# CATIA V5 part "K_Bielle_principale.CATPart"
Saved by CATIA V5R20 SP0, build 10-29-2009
Part number: Bielle_principale
Bounding box of the stored display mesh (mm): x -665 to -75.005, y -279.606 to -5, z 35.005 to 253.803
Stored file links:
  G:\Khaled_CFAO_2011\ST2M\ST2M_GR2\jcoetard\Khaled\CAD_CATIA\K_Bielle_principale.CATPart
  J:\Thinkmotion\Thinkmotion_COETARD\Maquette_catia\Maquette_catia_R20_Licence_education\jcharlescoetard.CATPRODUCT\Assemblage_Pince_Prehension_Mors_Paralleles.CATProduct
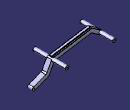
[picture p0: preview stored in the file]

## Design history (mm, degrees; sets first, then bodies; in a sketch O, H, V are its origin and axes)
Set1
  Plane1 "Plan_bielle_principale": linked copy from another document
  Point1 to Point3: linked copy from another document
Body1 (main body)
  Sketch1 on Plane1, origin (0, -122.303, 0), H (-1, 0, 0), V (0, 0, 1)
    construction line L1 (90, 50) -> (204.738, 94.0206)
    point P2 (204.738, 94.0206)
    line L2 (84.627, 64.0047) -> (187.0671, 103.307)
    line L3 (210.111, 80.0159) -> (95.373, 35.9953)
    arc A1 centre (90, 50) radius 15 from (95.373, 35.9953) to (84.627, 64.0047) cw
    construction line L4 (204.738, 94.0206) -> (250, 180)
    point P6 (204.738, 94.0206)
    line L5 (197.6006, 112.6634) -> (236.7268, 186.9874)
    line L6 (255.0898, 157.4677) -> (218.0112, 87.0332)
    arc A2 centre (250, 180) radius 15 from (236.7268, 186.9874) to (247.6716, 194.8182) cw
    arc A3 centre (204.738, 94.0206) radius 15 from (218.0112, 87.0332) to (210.111, 80.0159) cw
    construction line L7 (250, 180) -> (576, 231.225)
    point P11 (576, 231.225)
    line L8 (247.6716, 194.8182) -> (573.6716, 246.0432)
    line L9 (564.4914, 214.2326) -> (269.6828, 167.9088)
    arc A4 centre (576, 231.225) radius 15 from (573.6716, 246.0432) to (584.5375, 243.5583) cw
    construction line L10 (576, 231.225) -> (650, 180)
    point P14 (576, 231.225)
    line L11 (584.5375, 243.5583) -> (658.5375, 192.3333)
    line L12 (641.4625, 167.6667) -> (578.9792, 210.9194)
    arc A5 centre (650, 180) radius 15 from (658.5375, 192.3333) to (641.4625, 167.6667) cw
    arc A6 centre (179.9031, 121.9799) radius 20 from (187.0671, 103.307) to (197.6006, 112.6634) ccw
    point P21 (179.9031, 121.9799)
    arc A7 centre (272.7874, 148.1512) radius 20 from (255.0898, 157.4677) to (269.6828, 167.9088) cw
    point P24 (272.7874, 148.1512)
    arc A8 centre (567.5959, 194.475) radius 20 from (564.4914, 214.2326) to (578.9792, 210.9194) cw
    point P27 (567.5959, 194.475)
    reference projected point E1 (250, 180) from Point1
    reference projected point E2 (90, 50) from Point2
    reference projected point E3 (250, 180) from Point1
    reference projected point E4 (650, 180) from Point3
    distance L2 L3 = 30
    distance L5 L6 = 30
    distance L8 L9 = 30
    distance L11 L12 = 30
    radius A6 = 20
    radius A7 = 20
    radius A8 = 20
    distance P6 P21 = 37.3965
    distance P24 E1 = 39.1614
    distance P27 L10 = 35
    tangency: A1 L2, A1 L3, A2 L5, A3 L5, A2 L6, A3 L6, A4 L8, A4 L9, A5 L11, A5 L12, A6 L2, A6 L5, A7 L6, A7 L9, A8 L9, A8 L12, A2 L8, L3 A3, L11 A4
    coincidence: P6 P2, P14 P11
    concentricity: A1 E2, A2 E3, A5 E4
  Pad1: profile Sketch1, direction (0, -1, 0), length 40
  Sketch2 on start face of Pad1, origin (-60, -122.303, 50), H (1, 0, 0), V (0, 0, -1)
    point P1 (-30, 0)
    reference projected point E1 (-30, 0) from Point2
    coincidence: E1 P1
  Hole1: placed by Sketch2, at (-90, -122.303, 50) direction (0, -1, 0), diameter 10, depth 50
  Sketch3 on start face of Pad1, origin (0, -122.303, 0), H (-1, 0, 0), V (0, 0, 1)
    circle A1 centre (250, 180) radius 15
    point P1 (250, 180)
    reference projected point E1 (250, 180) from Point1
    reference projected arc E2 centre (250, 180) radius 15 from (247.339, 194.7621) to (236.5731, 186.6871) ccw from edge [face of Pad1 from Sketch1.A2 | start face of Pad1]
    circle A2 centre (650, 180) radius 15
    point P2 (650, 180)
    reference projected point E3 (650, 180) from Point3
    reference projected arc E4 centre (650, 180) radius 15 from (641.742, 167.4778) to (658.258, 192.5222) ccw from edge [face of Pad1 from Sketch1.A5 | start face of Pad1]
    coincidence: P1 E1, P2 E3
    tangency: A1 E2, A2 E4
  Pad2: profile Sketch3, direction (0, 1, 0), length 117.303
  Sketch4 on end face of Pad2, origin (-230, -5, 180), H (1, 0, 0), V (0, 0, -1)
    point P1 (-20, 0)
    reference projected point E1 (-20, 0) from Point1
    coincidence: E1 P1
  Hole2: placed by Sketch4, at (-250, -5, 180) direction (0, -1, 0), diameter 10, depth 300
  Sketch5 on end face of Pad2, origin (-580, -5, 180), H (1, 0, 0), V (0, 0, -1)
    point P1 (-70, 0)
    reference projected point E1 (-70, 0) from Point3
    coincidence: E1 P1
  Hole3: placed by Sketch5, at (-650, -5, 180) direction (0, -1, 0), diameter 10, depth 200
  Sketch6 on end face of Pad1, origin (0, -162.303, 0), H (1, 0, 0), V (0, 0, 1)
    circle A1 centre (-250, 180) radius 15
    point P1 (-250, 180)
    reference projected point E1 (-250, 180) from Point1
    reference projected arc E2 centre (-250, 180) radius 15 from (-236.6388, 186.8175) to (-247.4828, 194.7873) ccw from edge [end face of Pad1 | face of Pad2]
    circle A2 centre (-650, 180) radius 15
    point P2 (-650, 180)
    reference projected point E3 (-650, 180) from Point3
    reference projected arc E4 centre (-650, 180) radius 15 from (-658.3795, 192.4412) to (-641.6205, 167.5588) ccw from edge [end face of Pad1 | face of Pad1 from Sketch1.A5]
    coincidence: P1 E1, P2 E3
    tangency: E2 A1, A2 E4
  Pad3: profile Sketch6, direction (0, -1, 0), length 117.303
  Sketch7 on end face of Pad3, origin (-220, -279.606, 230), H (1, 0, 0), V (0, 0, 1)
    point P1 (-30, -50)
    reference projected point E1 (-30, -50) from Point1
    coincidence: E1 P1
  Hole4: placed by Sketch7, at (-250, -279.606, 180) direction (0, 1, 0), diameter 10, depth 300
  Sketch8 on end face of Pad3, origin (-590, -279.606, 230), H (1, 0, 0), V (0, 0, 1)
    point P1 (-60, -50)
    reference projected point E1 (-60, -50) from Point3
    coincidence: E1 P1
  Hole5: placed by Sketch8, at (-650, -279.606, 180) direction (0, 1, 0), diameter 10, depth 300
  Sketch9 on face of Pad1 from Sketch1.L8, origin (26.3115, 0, 151.7667), H (0, 1, 0), V (-0.9879, 0, 0.1552)
    line L1 (-152.303, 607.3449) -> (-132.303, 607.3449)
    line L2 (-132.303, 607.3449) -> (-132.303, 277.3449)
    line L3 (-132.303, 277.3449) -> (-152.303, 277.3449)
    line L4 (-152.303, 277.3449) -> (-152.303, 607.3449)
    reference projected line E1 (-122.303, 603.3583) -> (-122.303, 273.3583) from edge [face of Pad1 from Sketch1.L8 | start face of Pad1]
    reference projected line E2 (-162.303, 603.3583) -> (-162.303, 273.3583) from edge [end face of Pad1 | face of Pad1 from Sketch1.L8]
    reference projected line E3 (-122.303, 607.3449) -> (-162.303, 607.3449) from edge [face of Pad1 from Sketch1.A4 | face of Pad1 from Sketch1.L8]
    reference projected line E4 (-122.303, 277.3449) -> (-162.303, 277.3449) from edge [face of Pad1 from Sketch1.L8 | face of Pad2]
    distance L2 E1 = 10
    distance L4 E2 = 10
    horizontal: L1 H, L3 H
    vertical: L2 V, L4 V
    coincidence: L1 E3, L3 E4
  Pad4: profile Sketch9, direction (0.1552, 0, 0.9879), length 8
  Fillet1: radius 1, on end face of Pad4
  Fillet2: radius 0.5, on edge [face of Pad1 from Sketch1.L8 | face of Pad4 from Sketch9.L2]; edge [face of Pad1 from Sketch1.A4 | face of Pad4 from Sketch9.L1]; edge [face of Pad1 from Sketch1.L8 | face of Pad4 from Sketch9.L4]; edge [face of Pad4 from Sketch9.L3 | face of Pad2]
  Fillet3: radius 2, on edge [end face of Pad1 | face of Pad1 from Sketch1.L8]
  Fillet4: radius 2, on edge [face of Pad1 from Sketch1.L8 | start face of Pad1]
